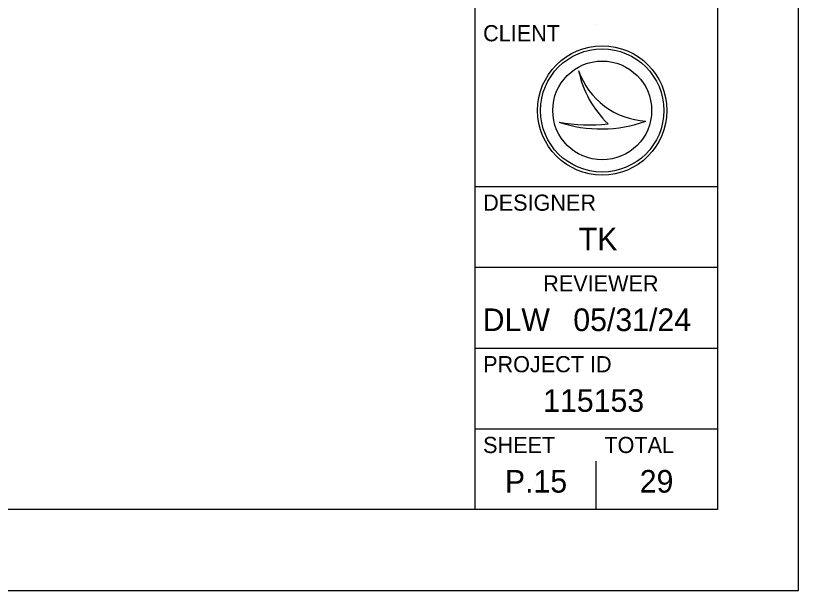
# Model space of a CAD drawing. Extents: x -4.7 to 34, y 0 to 22.
# Drawn here: x 29.158 to 34, y 0 to 3.557 of the extents above; entities that cross this region are included whole.
import ezdxf

# ---------------------------------------------------------------- set-up
doc = ezdxf.new("R2010")
doc.units = 0
for name, color, linetype in [('PF_X_Ground_Line', 7, 'Continuous'), ('UT_X_Gas', 7, 'Continuous'), ('UT_X_Misc_Cells', 7, 'Continuous'), ('UT_X_Water', 7, 'Continuous')]:
    doc.layers.add(name, color=color, linetype=linetype)

msp = doc.modelspace()

# ---------------------------------------------------------------- linework, layer by layer
at = {"layer": 'PF_X_Ground_Line'}
for p, q in [((32.75, 3.5), (32.75, 3.5)), ((32.6406, 3.218), (32.6406, 3.218)), ((33.0565, 2.9052), (33.0565, 2.9052)), ((32.5204, 2.898), (32.5204, 2.898)), ((32.75, 0.5), (32.75, 0.8)), ((32.375, 0.675), (32.375, 0.675))]:
    msp.add_line(p, q, dxfattribs=at)
for radius in [0.4, 0.3814, 0.3814, 0.3058]:
    msp.add_circle((32.7867, 2.9704), radius, dxfattribs=at)
for centre, radius, start, end in [((33.0794, 3.3685), 0.4639, 198.9257, 198.9319), ((33.264, 3.3464), 0.6365, 191.6379, 191.6421), ((33.0794, 3.3685), 0.4639, 198.9319, 267.1657), ((33.264, 3.3464), 0.6365, 191.6421, 226.0947), ((32.7782, 3.6664), 0.8105, 251.4576, 290.0832), ((32.7051, 3.8938), 1.0128, 259.4964, 259.4995), ((32.7782, 3.6664), 0.8105, 251.4527, 251.4576), ((32.7051, 3.8938), 1.0128, 259.4995, 276.6672)]:
    msp.add_arc(centre, radius, start, end, dxfattribs=at)
at = {"layer": 'UT_X_Misc_Cells'}
msp.add_lwpolyline([(0, 0), (34, 0), (34, 22), (0, 22)], close=True, dxfattribs=at)
at = {"layer": 'UT_X_Water'}
for p, q in [((32, 0.5), (32, 21.5)), ((32, 2.5), (33.5, 2.5)), ((32, 2), (33.5, 2)), ((32, 1.5), (33.5, 1.5)), ((32, 1), (33.5, 1))]:
    msp.add_line(p, q, dxfattribs=at)
msp.add_lwpolyline([(1.5, 21.5), (33.5, 21.5), (33.5, 0.5), (1.5, 0.5)], close=True, dxfattribs=at)

# ---------------------------------------------------------------- texts
at = {"layer": 'PF_X_Ground_Line'}
for s, height, p in [('DESIGNER', 0.1, (32.05, 2.35)), ('TK', 0.14, (32.6415, 2.105)), ('REVIEWER', 0.1, (32.4218, 1.85)), ('DLW', 0.14, (32.0474, 1.605)), ('05/31/24', 0.14, (32.6078, 1.605)), ('PROJECT ID', 0.1, (32.05, 1.35)), ('115153', 0.14, (32.4215, 1.105)), ('SHEET', 0.1, (32.05, 0.85)), ('TOTAL', 0.1, (32.8, 0.85)), ('P.15', 0.14, (32.1848, 0.605)), ('29', 0.14, (33.0188, 0.605))]:
    msp.add_text(s, height=height, dxfattribs=at).set_placement(p)
at = {"layer": 'UT_X_Gas'}
msp.add_text('CLIENT', height=0.1, dxfattribs=at).set_placement((32.05, 3.3986))

doc.saveas('drawing.dxf')
